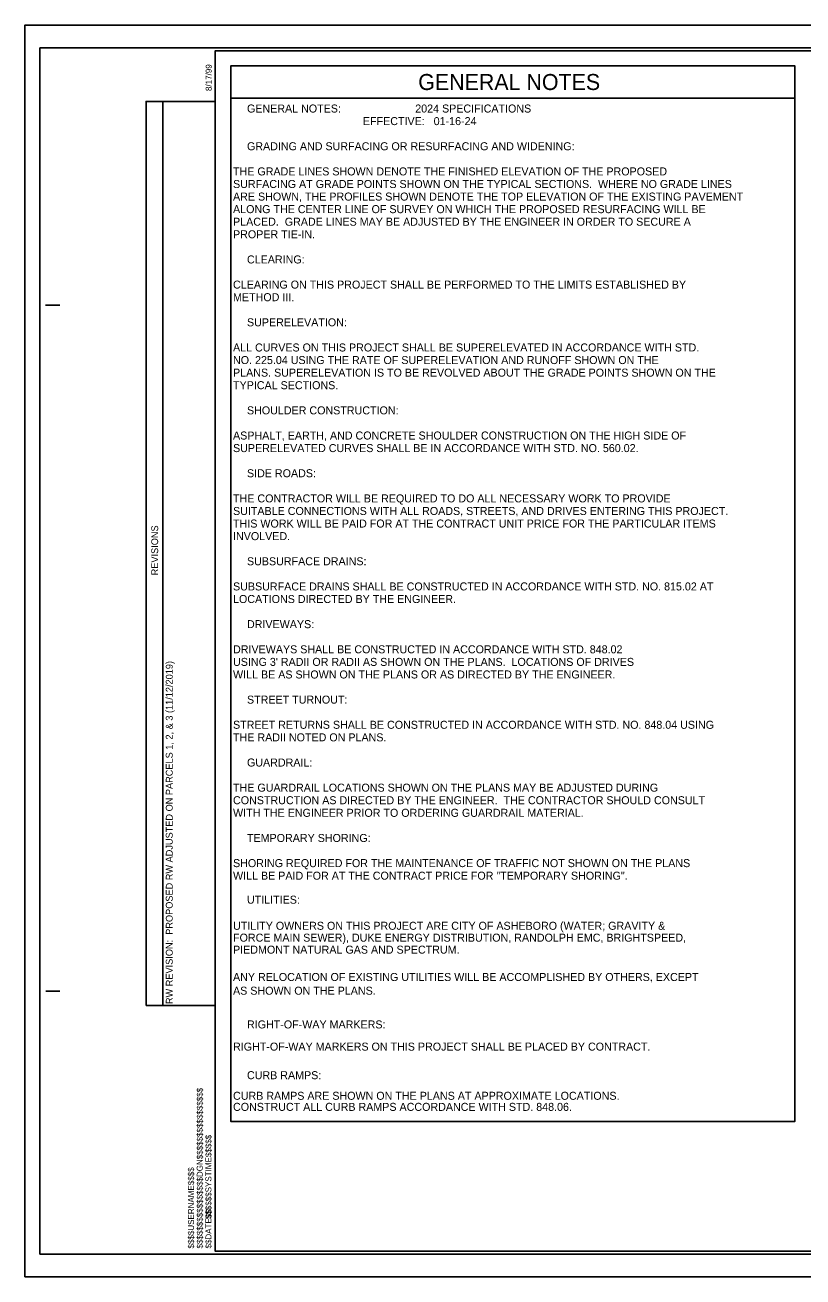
# Model space of a CAD drawing. Extents: x 5863093 to 5864777, y 1244886 to 1246112.
# Drawn here: x 5863093 to 5863774, y 1245017 to 1246112 of the extents above; entities that cross this region are included whole.
import ezdxf

# ---------------------------------------------------------------- set-up
doc = ezdxf.new("R2010")
doc.units = 0
for name, color, linetype in [('Old_Level_1', 7, 'Continuous'), ('Old_Level_40', 7, 'Continuous'), ('Old_Level_41', 7, 'Continuous'), ('Sheet Block Revision CELL', 7, 'Continuous'), ('Sheet Cutting Line CELL', 7, 'Continuous'), ('Sheet Plan CELL', 7, 'Continuous'), ('Sheet Plot Border Inside CELL', 7, 'Continuous'), ('Sheet Plot Border Outside CELL', 7, 'Continuous')]:
    doc.layers.add(name, color=color, linetype=linetype)

msp = doc.modelspace()

# ---------------------------------------------------------------- linework, layer by layer
at = {"layer": 'Old_Level_1'}
msp.add_lwpolyline([(5863273.3, 1246047.7), (5863766.9, 1246047.7), (5863766.9, 1245152.6), (5863273.3, 1245152.6)], close=True, dxfattribs=at)
at = {"layer": 'Old_Level_40'}
msp.add_lwpolyline([(5863273.3, 1246047.7), (5863766.9, 1246047.7), (5863766.9, 1246075.7), (5863273.3, 1246075.7)], close=True, dxfattribs=at)
at = {"layer": 'Sheet Block Revision CELL'}
msp.add_line((5863213.9, 1245254), (5863213.8, 1246044.7), dxfattribs=at)
msp.add_lwpolyline([(5863199.3, 1245254), (5863199.3, 1246044.7), (5863259.8, 1246044.7), (5863259.8, 1245254)], close=True, dxfattribs=at)
at = {"layer": 'Sheet Cutting Line CELL'}
for p, q in [((5864776.8, 1246111.5), (5863093.3, 1246111.5)), ((5863093.3, 1246111.5), (5863093.3, 1245016.5)), ((5863093.3, 1245016.5), (5864776.8, 1245016.5))]:
    msp.add_line(p, q, dxfattribs=at)
at = {"layer": 'Sheet Plan CELL'}
for p, q in [((5863259.8, 1246089), (5863259.8, 1246089)), ((5863111.3, 1245866.5), (5863123.8, 1245866.5)), ((5863111.4, 1245266.5), (5863123.9, 1245266.5)), ((5863259.8, 1245039), (5863259.8, 1245039))]:
    msp.add_line(p, q, dxfattribs=at)
for points in [[(5863259.8, 1245039), (5863259.8, 1246089), (5864559.8, 1246089.1), (5864559.8, 1245939), (5864759.8, 1245939), (5864759.8, 1245039)], [(5864759.9, 1246089), (5863259.8, 1246089), (5863259.8, 1245039), (5864759.8, 1245039)]]:
    msp.add_lwpolyline(points, close=True, dxfattribs=at)
at = {"layer": 'Sheet Plot Border Inside CELL'}
msp.add_lwpolyline([(5863106.3, 1245036.5), (5864772.3, 1245036.5), (5864772.3, 1246091.5), (5863106.3, 1246091.5)], close=True, dxfattribs=at)
at = {"layer": 'Sheet Plot Border Outside CELL'}
msp.add_lwpolyline([(5863093.3, 1245016.5), (5864776.8, 1245016.5), (5864776.8, 1246111.5), (5863093.3, 1246111.5)], close=True, dxfattribs=at)

# ---------------------------------------------------------------- texts
at = {"layer": 'Old_Level_1'}
for s, p in [('GENERAL NOTES:                         2024 SPECIFICATIONS', (5863287.5, 1246035)), ('                                       EFFECTIVE:   01-16-24', (5863287.5, 1246024)), ('GRADING AND SURFACING OR RESURFACING AND WIDENING:  ', (5863287.5, 1246002)), ('         THE GRADE LINES SHOWN DENOTE THE FINISHED ELEVATION OF THE PROPOSED ', (5863251.9, 1245980)), ('         SURFACING AT GRADE POINTS SHOWN ON THE TYPICAL SECTIONS.  WHERE NO GRADE LINES ', (5863251.9, 1245969)), ('         ARE SHOWN, THE PROFILES SHOWN DENOTE THE TOP ELEVATION OF THE EXISTING PAVEMENT', (5863251.9, 1245958)), ('         ALONG THE CENTER LINE OF SURVEY ON WHICH THE PROPOSED RESURFACING WILL BE ', (5863251.9, 1245947)), ('         PLACED.  GRADE LINES MAY BE ADJUSTED BY THE ENGINEER IN ORDER TO SECURE A ', (5863251.9, 1245936)), ('         PROPER TIE-IN. ', (5863251.9, 1245925)), ('CLEARING:  ', (5863287.5, 1245903)), ('         CLEARING ON THIS PROJECT SHALL BE PERFORMED TO THE LIMITS ESTABLISHED BY ', (5863251.9, 1245881)), ('         METHOD III.', (5863251.9, 1245870)), ('SUPERELEVATION:  ', (5863287.5, 1245848)), ('         ALL CURVES ON THIS PROJECT SHALL BE SUPERELEVATED IN ACCORDANCE WITH STD. ', (5863251.9, 1245826)), ('         NO. 225.04 USING THE RATE OF SUPERELEVATION AND RUNOFF SHOWN ON THE', (5863251.9, 1245815)), ('         PLANS. SUPERELEVATION IS TO BE REVOLVED ABOUT THE GRADE POINTS SHOWN ON THE', (5863251.9, 1245804)), ('         TYPICAL SECTIONS.  ', (5863251.9, 1245793)), ('SHOULDER CONSTRUCTION:  ', (5863287.5, 1245771)), ('         ASPHALT, EARTH, AND CONCRETE SHOULDER CONSTRUCTION ON THE HIGH SIDE OF', (5863251.9, 1245749)), ('         SUPERELEVATED CURVES SHALL BE IN ACCORDANCE WITH STD. NO. 560.02.', (5863251.9, 1245738)), ('SIDE ROADS:', (5863287.5, 1245716)), ('         THE CONTRACTOR WILL BE REQUIRED TO DO ALL NECESSARY WORK TO PROVIDE ', (5863251.9, 1245694)), ('         SUITABLE CONNECTIONS WITH ALL ROADS, STREETS, AND DRIVES ENTERING THIS PROJECT.  ', (5863251.9, 1245683)), ('         THIS WORK WILL BE PAID FOR AT THE CONTRACT UNIT PRICE FOR THE PARTICULAR ITEMS ', (5863251.9, 1245672)), ('         INVOLVED.  ', (5863251.9, 1245661)), ('SUBSURFACE DRAINS:', (5863287.5, 1245639)), ('         SUBSURFACE DRAINS SHALL BE CONSTRUCTED IN ACCORDANCE WITH STD. NO. 815.02 AT ', (5863251.9, 1245617)), ('         LOCATIONS DIRECTED BY THE ENGINEER.  ', (5863251.9, 1245606)), ('DRIVEWAYS:  ', (5863287.5, 1245584)), ('         DRIVEWAYS SHALL BE CONSTRUCTED IN ACCORDANCE WITH STD. 848.02', (5863251.9, 1245562)), ("         USING 3' RADII OR RADII AS SHOWN ON THE PLANS.  LOCATIONS OF DRIVES", (5863251.9, 1245551)), ('         WILL BE AS SHOWN ON THE PLANS OR AS DIRECTED BY THE ENGINEER.  ', (5863251.9, 1245540)), ('STREET TURNOUT:  ', (5863287.5, 1245518)), ('         STREET RETURNS SHALL BE CONSTRUCTED IN ACCORDANCE WITH STD. NO. 848.04 USING', (5863251.9, 1245496)), ('         THE RADII NOTED ON PLANS.', (5863251.9, 1245485)), ('GUARDRAIL:  ', (5863287.5, 1245463)), ('         THE GUARDRAIL LOCATIONS SHOWN ON THE PLANS MAY BE ADJUSTED DURING ', (5863251.9, 1245441)), ('         CONSTRUCTION AS DIRECTED BY THE ENGINEER.  THE CONTRACTOR SHOULD CONSULT', (5863251.9, 1245430)), ('         WITH THE ENGINEER PRIOR TO ORDERING GUARDRAIL MATERIAL.', (5863251.9, 1245419)), ('TEMPORARY SHORING:  ', (5863287.5, 1245397)), ('         SHORING REQUIRED FOR THE MAINTENANCE OF TRAFFIC NOT SHOWN ON THE PLANS ', (5863251.9, 1245375)), ('         WILL BE PAID FOR AT THE CONTRACT PRICE FOR "TEMPORARY SHORING".', (5863251.9, 1245364)), ('UTILITIES:  ', (5863287.5, 1245343)), ('         UTILITY OWNERS ON THIS PROJECT ARE CITY OF ASHEBORO (WATER; GRAVITY &', (5863251.9, 1245320.2)), ('         FORCE MAIN SEWER), DUKE ENERGY DISTRIBUTION, RANDOLPH EMC, BRIGHTSPEED,', (5863251.9, 1245309.8)), ('         PIEDMONT NATURAL GAS AND SPECTRUM.', (5863251.9, 1245299.3)), ('         ANY RELOCATION OF EXISTING UTILITIES WILL BE ACCOMPLISHED BY OTHERS, EXCEPT ', (5863251.9, 1245275.4)), ('         AS SHOWN ON THE PLANS.  ', (5863251.9, 1245263.4)), ('RIGHT-OF-WAY MARKERS:  ', (5863287.5, 1245233.9)), ('         RIGHT-OF-WAY MARKERS ON THIS PROJECT SHALL BE PLACED BY CONTRACT.', (5863251.9, 1245214.5)), ('CURB RAMPS:  ', (5863287.5, 1245189.5)), ('         CURB RAMPS ARE SHOWN ON THE PLANS AT APPROXIMATE LOCATIONS.', (5863251.9, 1245171.5)), ('         CONSTRUCT ALL CURB RAMPS ACCORDANCE WITH STD. 848.06.', (5863251.9, 1245161.8))]:
    msp.add_text(s, height=7, dxfattribs=at).set_placement(p)
at = {"layer": 'Old_Level_40'}
msp.add_text('GENERAL NOTES', height=14, dxfattribs=at).set_placement((5863437.3, 1246054.7))
at = {"layer": 'Old_Level_41'}
for s, p in [('$$$$$$$$$$$$$$$$DGN$$$$$$$$$$$$$$$$', (5863248.8, 1245041.4)), ('$$$$$$SYSTIME$$$$$', (5863256.4, 1245067.1)), ('$$$$USERNAME$$$$', (5863241.2, 1245041.4)), ('$$DATE$$', (5863256.4, 1245041.4))]:
    msp.add_text(s, height=5.25, rotation=90, dxfattribs=at).set_placement(p)
at = {"layer": 'Sheet Block Revision CELL'}
for s, p in [('REVISIONS', (5863209.8, 1245630.2)), ('RW REVISION:  PROPOSED RW ADJUSTED ON PARCELS 1, 2, & 3 (11/12/2019)', (5863222.5, 1245255.2))]:
    msp.add_text(s, height=6, rotation=90, dxfattribs=at).set_placement(p)
at = {"layer": 'Sheet Plan CELL'}
msp.add_text('8/17/99', height=5.25, rotation=90, dxfattribs=at).set_placement((5863256.6, 1246053.8))

doc.saveas('drawing.dxf')
